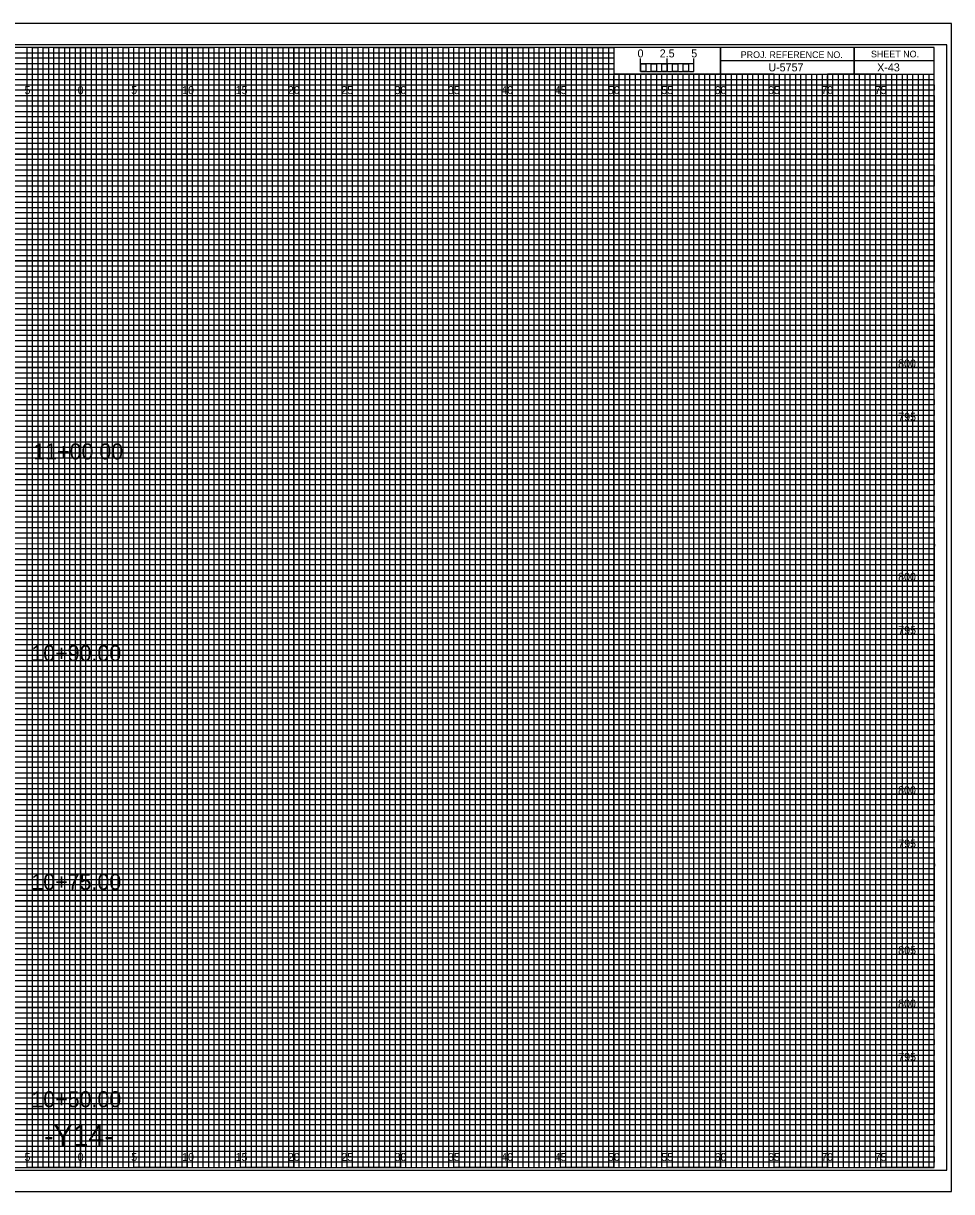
# Model space of a CAD drawing. Extents: x -7 to 162, y -2 to 107.
# Drawn here: x 74.6 to 161.7, y -2.3 to 107.3 of the extents above; entities that cross this region are included whole.
import ezdxf

# ---------------------------------------------------------------- set-up
doc = ezdxf.new("R2010")
doc.units = 0
for name, color, linetype in [('Exist CMT Pavement', 7, 'Continuous'), ('Exist Cross Section Cell', 7, 'Continuous'), ('Exist XS Center Line Elevation Label', 7, 'Continuous'), ('Prop CMT Conc Surface', 7, 'Continuous'), ('Prop CMT Concrete Structures', 7, 'Continuous'), ('Prop CMT Pvmt Course 1 CG', 7, 'Continuous'), ('Prop CMT Pvmt Course 2 Wedge', 7, 'Continuous'), ('Prop XS Alignment Label', 7, 'Continuous'), ('Prop XS Bar Scale Labels', 7, 'Continuous'), ('Prop XS Hydro Elevations', 7, 'Continuous'), ('Prop XS SE Text', 7, 'Continuous'), ('Prop XS Side Slope Text', 7, 'Continuous'), ('Sheet Cross Section Grid Minor 2 CELL', 7, 'Continuous'), ('Sheet Cross Section Scale CELL', 7, 'Continuous'), ('Sheet DOT Grid CELL', 7, 'Continuous'), ('Sheet Plot Border Inside CELL', 7, 'Continuous'), ('Sheet Plot Border Outside CELL', 7, 'Continuous')]:
    doc.layers.add(name, color=color, linetype=linetype)

msp = doc.modelspace()

# ---------------------------------------------------------------- linework, layer by layer
at = {"layer": 'Exist Cross Section Cell'}
for p, q in [((75, 105), (70, 105)), ((75, 0), (75, 105)), ((85, 105), (80, 105)), ((80, 105), (80, 0)), ((85, 0), (85, 105)), ((95, 105), (90, 105)), ((90, 105), (90, 0)), ((95, 0), (95, 105)), ((105, 105), (100, 105)), ((100, 105), (100, 0)), ((105, 0), (105, 105)), ((115, 105), (110, 105)), ((110, 105), (110, 0)), ((115, 0), (115, 105)), ((125, 105), (120, 105)), ((120, 105), (120, 0)), ((125, 0), (125, 105)), ((130, 105), (130, 0)), ((135, 0), (135, 102.5)), ((145, 102.5), (140, 102.5)), ((140, 102.5), (140, 0)), ((145, 0), (145, 102.5)), ((155, 102.5), (150, 102.5)), ((150, 102.5), (150, 0)), ((155, 0), (155, 102.5)), ((80, 0), (75, 0)), ((90, 0), (85, 0)), ((100, 0), (95, 0)), ((110, 0), (105, 0)), ((120, 0), (115, 0)), ((130, 0), (125, 0)), ((140, 0), (135, 0)), ((150, 0), (145, 0)), ((160, 0), (155, 0)), ((160, 0), (160, 0))]:
    msp.add_line(p, q, dxfattribs=at)
for points in [[(0, 100), (160, 100), (160, 95), (0, 95)], [(0, 90), (160, 90), (160, 85), (0, 85)], [(0, 80), (160, 80), (160, 75), (0, 75)], [(0, 70), (160, 70), (160, 65), (0, 65)], [(0, 60), (160, 60), (160, 55), (0, 55)], [(0, 50), (160, 50), (160, 45), (0, 45)], [(0, 40), (160, 40), (160, 35), (0, 35)], [(0, 30), (160, 30), (160, 25), (0, 25)], [(0, 20), (160, 20), (160, 15), (0, 15)], [(0, 10), (160, 10), (160, 5), (0, 5)]]:
    msp.add_lwpolyline(points, dxfattribs=at)
at = {"layer": 'Exist XS Center Line Elevation Label'}
for points in [[(72.5, 0), (77.5, 0), (77.5, 105), (82.5, 105), (82.5, 0), (87.5, 0), (87.5, 105), (92.5, 105), (92.5, 0), (97.5, 0), (97.5, 105), (102.5, 105), (102.5, 0), (107.5, 0), (107.5, 105), (112.5, 105), (112.5, 0), (117.5, 0), (117.5, 105), (122.5, 105), (122.5, 0), (127.5, 0), (127.5, 105), (129.97, 105), (130, 105), (130, 102.5), (132.5, 102.5), (132.5, 0), (137.5, 0), (137.5, 102.5), (142.5, 102.5), (142.5, 0), (147.5, 0), (147.5, 102.5), (152.5, 102.5), (152.5, 0), (157.5, 0), (157.5, 102.5)], [(0, 102.5), (137.5, 102.5)], [(0, 92.5), (160, 92.5), (160, 97.5), (0, 97.5)], [(0, 82.5), (160, 82.5), (160, 87.5), (0, 87.5)], [(0, 72.5), (160, 72.5), (160, 77.5), (0, 77.5)], [(0, 62.5), (160, 62.5), (160, 67.5), (0, 67.5)], [(0, 52.5), (160, 52.5), (160, 57.5), (0, 57.5)], [(0, 42.5), (160, 42.5), (160, 47.5), (0, 47.5)], [(0, 32.5), (160, 32.5), (160, 37.5), (0, 37.5)], [(0, 22.5), (160, 22.5), (160, 27.5), (0, 27.5)], [(0, 12.5), (160, 12.5), (160, 17.5), (0, 17.5)], [(0, 2.5), (160, 2.5), (160, 7.5), (0, 7.5)]]:
    msp.add_lwpolyline(points, dxfattribs=at)
at = {"layer": 'Prop CMT Concrete Structures'}
for p, q in [((161.65, 107.25), (-6.7, 107.25)), ((-6.7, -2.25), (161.65, -2.25))]:
    msp.add_line(p, q, dxfattribs=at)
at = {"layer": 'Prop CMT Pvmt Course 2 Wedge'}
for p, q in [((152.5, 105), (152.5, 102.5)), ((152.5, 102.5), (152.5, 105)), ((160, 103.75), (140, 103.75)), ((140, 103.75), (140, 102.5)), ((140, 102.5), (160, 102.5))]:
    msp.add_line(p, q, dxfattribs=at)
for points in [[(160, 105), (0, 105), (0, 0), (160, 0)], [(140, 105), (130, 105), (130, 102.52), (140, 102.52)], [(160, 105), (140, 105), (140, 102.5), (160, 102.5)]]:
    msp.add_lwpolyline(points, close=True, dxfattribs=at)
at = {"layer": 'Prop XS Side Slope Text'}
for p, q in [((0, 104.5), (130, 104.5)), ((130, 104.5), (130, 103.99)), ((130, 103.99), (0, 103.99)), ((0, 103.5), (130, 103.5)), ((130, 102.95), (0, 102.95)), ((130, 103.5), (130, 102.95)), ((0, 102), (160, 102))]:
    msp.add_line(p, q, dxfattribs=at)
for points in [[(0, 101.5), (135, 101.5), (160, 101.5), (160, 101), (0, 101)], [(0, 100.5), (160, 100.5), (160, 99.5), (0, 99.5)], [(0, 99), (160, 99), (160, 98.5), (0, 98.49)], [(0, 98), (160, 98), (160, 97), (0, 97)], [(0, 96.5), (160, 96.5), (160, 96), (0, 96)], [(0, 95.5), (160, 95.5), (160, 94.5), (0, 94.5)], [(0, 94), (160, 94), (160, 93.5), (0, 93.5)], [(0, 93), (160, 93), (160, 92), (0, 92)], [(0, 91.5), (160, 91.5), (160, 91), (0, 91)], [(0, 90.5), (160, 90.5), (160, 89.5), (0, 89.5)], [(0, 89), (160, 89), (160, 88.5), (0, 88.5)], [(0, 88), (160, 88), (160, 86.98), (160, 86.5), (160, 86), (0, 86)], [(0, 87), (160, 87), (160, 86.5), (0, 86.5)], [(0, 85.5), (160, 85.5), (160, 84.5), (0, 84.52)], [(0, 84.52), (160, 84.5), (160, 84), (0, 84)], [(0, 83.5), (160, 83.5), (160, 83), (0, 83)], [(0, 82), (160, 82), (160, 81.5), (0, 81.5)], [(0, 81), (160, 81), (160, 80.5), (0, 80.5)], [(-0.04, 79.45), (160, 79.45), (160, 78.94), (-0.04, 78.94)], [(0, 78.5), (160, 78.5), (160, 78), (0, 78)], [(0, 77), (160, 77), (160, 76.5), (0, 76.5)], [(0, 76), (160, 76), (160, 75.5), (0, 75.5)], [(0, 74.5), (160, 74.5), (160, 74), (0, 74)], [(0, 73.5), (160, 73.5), (160, 73), (0, 73)], [(0, 72), (160, 72), (160, 71.5), (0, 71.5)], [(0, 71), (160, 71), (160, 70.5), (0, 70.5)], [(0, 69.5), (160, 69.5), (160, 68.99), (0, 69)], [(0, 68.5), (160, 68.5), (160, 68), (0, 68)], [(0, 67), (160, 67), (160, 66.5), (0, 66.5)], [(0, 66), (160, 66), (160, 65.5), (0, 65.5)], [(0, 64.5), (160, 64.5), (160, 64), (0, 64)], [(0, 63.5), (160, 63.5), (160, 63), (0, 63)], [(0, 62), (160, 62), (160, 61.5), (0, 61.5)], [(0, 61), (160, 61), (160, 60.5), (0, 60.5)], [(0, 59.5), (160, 59.5), (160, 59), (0, 59)], [(0, 58.5), (160.03, 58.45), (160, 58), (0, 58)], [(0, 57), (160, 57), (160, 56.5), (0, 56.5)], [(0, 56), (160, 56), (160, 55.5), (0, 55.5)], [(0, 54.5), (160, 54.5), (160, 54), (0, 54)], [(0, 53.5), (160, 53.5), (160, 53), (0, 53)], [(0, 52), (160, 52), (160, 51.5), (0, 51.5)], [(0, 51), (160, 51), (160, 50.5), (0, 50.5)], [(0, 49.5), (160, 49.5), (160, 49), (0, 49)], [(0, 48.5), (160, 48.5), (160, 48), (0, 48)], [(0, 47), (160, 47), (160, 46.5), (0, 46.5)], [(0, 46), (160, 46), (160, 45.5), (0, 45.5)], [(0, 44.5), (160, 44.5), (160, 44), (0, 44)], [(0, 43.5), (160, 43.5), (160, 43), (0, 43)], [(0, 42), (160, 42), (160, 41.5), (0, 41.5)], [(0, 41), (160, 41), (160, 40.5), (0, 40.5)], [(0, 39.5), (160, 39.5), (160, 38.99), (0, 39)], [(0, 38.5), (160, 38.5), (160, 38), (0, 38)], [(0, 37), (160, 37), (160, 36.5), (0, 36.5)], [(0, 36), (160, 36), (160, 35.5), (0, 35.5)], [(0, 34.5), (160, 34.5), (160, 34), (0, 34)], [(0, 33.5), (160, 33.5), (160, 33), (0, 33)], [(0, 32), (160, 32), (160, 31.5), (0, 31.5)], [(0, 31), (160, 31), (160, 30.5), (0, 30.5)], [(0, 29.5), (160, 29.5), (160, 29), (0, 29)], [(0, 28.5), (160.03, 28.46), (160, 28), (0, 28)], [(0, 27), (160, 27), (160, 26.5), (0, 26.5)], [(0, 26), (160, 26), (160, 25.5), (0, 25.5)], [(0, 24.5), (160, 24.5), (160, 24), (0, 24)], [(0, 23.5), (160, 23.5), (160, 23), (0, 23)], [(0, 22), (160, 22), (160, 21.5), (0, 21.5)], [(0, 21), (160, 21), (160, 20.5), (0, 20.5)], [(0, 19.5), (160, 19.5), (160, 19), (0, 19)], [(0, 18.5), (160, 18.5), (160, 18), (0, 18)], [(0, 17), (160, 17), (160, 16.5), (0, 16.5)], [(0, 16), (160, 16), (160, 15.5), (0, 15.5)], [(0, 14.5), (160, 14.5), (160, 14), (0, 14)], [(0, 13.5), (160, 13.5), (160, 13), (0, 13)], [(0, 12), (160, 12), (160, 11.5), (0, 11.5)], [(0, 11), (160, 11), (160, 10.5), (0, 10.5)], [(0, 9.5), (160, 9.5), (160, 9), (0, 9)], [(0, 8.5), (160, 8.5), (160, 8), (0, 8)], [(0, 7), (160, 7), (160, 6.5), (0, 6.5)], [(0, 6), (160, 6), (160, 5.5), (0, 5.5)], [(0, 4.5), (160, 4.5), (160, 4), (0, 4)], [(0, 3.5), (160, 3.5), (160, 3), (0, 3)], [(0, 2), (160, 2), (160, 1.5), (0, 1.5)], [(0, 1), (160, 1), (160, 0.5), (0, 0.5)]]:
    msp.add_lwpolyline(points, dxfattribs=at)
at = {"layer": 'Sheet Cross Section Grid Minor 2 CELL'}
for p, q in [((133.5, 102.5), (133, 102.5)), ((133, 102.5), (133, 0)), ((133.5, 0), (133.5, 102.5)), ((134.5, 102.5), (134, 102.5)), ((134, 102.5), (134, 0)), ((134.5, 0), (134.5, 102.5)), ((133, 0), (132.5, 0)), ((134, 0), (133.5, 0))]:
    msp.add_line(p, q, dxfattribs=at)
for points in [[(75, 0), (75.5, 0), (75.5, 105), (76, 105), (76, 0)], [(76, 0), (76.5, 0), (76.5, 105), (77, 105), (77, 0)], [(77.5, 0), (78, 0), (78, 105), (78.5, 105), (78.5, 0)], [(78.5, 0), (79, 0), (79, 105), (79.5, 105), (79.5, 0)], [(80, 0), (80.5, 0), (80.5, 105), (81, 105), (81, 0)], [(81, 0), (81.5, 0), (81.5, 105), (82, 105), (82, 0)], [(82.5, 0), (83, 0), (83, 105), (83.5, 105), (83.5, 0)], [(83.5, 0), (84, 0), (84, 105), (84.5, 105), (84.5, 0)], [(85, 0), (85.5, 0), (85.5, 105), (86, 105), (86, 0)], [(86, 0), (86.5, 0), (86.5, 105), (87, 105), (87, 0)], [(87.5, 0), (88, 0), (88, 105), (88.5, 105), (88.5, 0)], [(88.5, 0), (89, 0), (89, 105), (89.5, 105), (89.5, 0)], [(90, 0), (90.5, 0), (90.5, 105), (91, 105), (91, 0)], [(91, 0), (91.5, 0), (91.5, 105), (92, 105), (92, 0)], [(92.5, 0), (93, 0), (93, 105), (93.5, 105), (93.5, 0)], [(93.5, 0), (94, 0), (94, 105), (94.5, 105), (94.5, 0)], [(95, 0), (95.5, 0), (95.5, 105), (96, 105), (96, 0)], [(96, 0), (96.5, 0), (96.5, 105), (97, 105), (97, 0)], [(97.5, 0), (98, 0), (98, 105), (98.5, 105), (98.5, 0)], [(98.5, 0), (99, 0), (99, 105), (99.5, 105), (99.5, 0)], [(100, 0), (100.5, 0), (100.5, 105), (101, 105), (101, 0)], [(101, 0), (101.5, 0), (101.5, 105), (102, 105), (102, 0)], [(102.5, 0), (103, 0), (103, 105), (103.5, 105), (103.5, 0)], [(103.5, 0), (104, 0), (104, 105), (104.5, 105), (104.5, 0)], [(105, 0), (105.5, 0), (105.5, 105), (106, 105), (106, 0)], [(106, 0), (106.5, 0), (106.5, 105), (107, 105), (107, 0)], [(107.5, 0), (108, 0), (108, 105), (108.5, 105), (108.5, 0)], [(108.5, 0), (109, 0), (109, 105), (109.5, 105), (109.5, 0)], [(110, 0), (110.5, 0), (110.5, 105), (111, 105), (111, 0)], [(111, 0), (111.5, 0), (111.5, 105), (112, 105), (112, 0)], [(112.5, 0), (113, 0), (113, 105), (113.5, 105), (113.5, 0)], [(113.5, 0), (114, 0), (114, 105), (114.5, 105), (114.5, 0)], [(115, 0), (115.5, 0), (115.5, 105), (116, 105), (116, 0)], [(116, 0), (116.5, 0), (116.5, 105), (117, 105), (117, 0)], [(117.5, 0), (118, 0), (118, 105), (118.5, 105), (118.5, 0)], [(118.5, 0), (119, 0), (119, 105), (119.5, 105), (119.5, 0)], [(120, 0), (120.5, 0), (120.5, 105), (121, 105), (121, 0)], [(121, 0), (121.5, 0), (121.5, 105), (122, 105), (122, 0)], [(122.5, 0), (123, 0), (123, 105), (123.5, 105), (123.5, 0)], [(123.5, 0), (124, 0), (124, 105), (124.5, 105), (124.5, 0)], [(125, 0), (125.5, 0), (125.5, 105), (126, 105), (126, 0)], [(126, 0), (126.5, 0), (126.5, 105), (127, 105), (127, 0)], [(127.5, 0), (128, 0), (128, 105), (128.5, 105), (128.5, 0)], [(128.5, 0), (129, 0), (129, 105), (129.5, 105), (129.5, 0)], [(130, 0), (130.5, 0), (130.5, 102.5), (131.01, 102.5), (131.01, 0)], [(131, 0), (131.5, 0), (131.5, 102.5), (132, 102.5), (132, 0)], [(135, 0), (135.49, 0), (135.49, 102.5), (136, 102.5), (136, 0)], [(136, 0), (136.5, 0), (136.5, 102.5), (137.03, 102.5), (137.03, 0)], [(137.5, 0), (138, 0), (138, 102.5), (138.5, 102.5), (138.5, 0)], [(138.5, 0), (139, 0), (139, 102.5), (139.5, 102.5), (139.5, 0)], [(140, 0), (140.5, 0), (140.5, 102.5), (141, 102.5), (141, 0)], [(141, 0), (141.5, 0), (141.5, 102.5), (142, 102.5), (142, 0)], [(142.5, 0), (143, 0), (143, 102.5), (143.5, 102.5), (143.5, 0)], [(143.5, 0), (144, 0), (144, 102.5), (144.5, 102.5), (144.5, 0)], [(145, 0), (145.5, 0), (145.5, 102.5), (146, 102.5), (146, 0)], [(146, 0), (146.5, 0), (146.5, 102.5), (147, 102.5), (147, 0)], [(147.5, 0), (148, 0), (148, 102.5), (148.5, 102.5), (148.5, 0)], [(148.5, 0), (149, 0), (149, 102.5), (149.5, 102.5), (149.5, 0)], [(150, 0), (150.5, 0), (150.5, 102.5), (151, 102.5), (151, 0)], [(151, 0), (151.5, 0), (151.5, 102.5), (152, 102.5), (152, 0)], [(152.5, 0), (153, 0), (153, 102.5), (153.5, 102.5), (153.5, 0)], [(153.5, 0), (154, 0), (154, 102.5), (154.5, 102.5), (154.5, 0)], [(155, 0), (155.5, 0), (155.5, 102.5), (156, 102.5), (156, 0)], [(156, 0), (156.5, 0), (156.5, 102.5), (157, 102.5), (157, 0)], [(157.5, 0), (158, 0), (158, 102.5), (158.5, 102.5), (158.5, 0)], [(158.5, 0), (159, 0), (159, 102.5), (159.5, 102.5), (159.5, 0)]]:
    msp.add_lwpolyline(points, dxfattribs=at)
at = {"layer": 'Sheet Cross Section Scale CELL'}
for p, q in [((132.5, 102.75), (132.5, 103.95)), ((132.5, 103.45), (132.5, 103.95)), ((135, 102.75), (135, 103.95)), ((137.5, 102.75), (137.5, 103.95)), ((137.5, 103.45), (137.5, 103.95))]:
    msp.add_line(p, q, dxfattribs=at)
for points in [[(137.5, 103.45), (132.5, 103.45), (132.5, 102.75), (137.5, 102.75)], [(132.5, 103.45), (133, 103.45), (133, 102.75), (132.5, 102.75)], [(133.5, 103.45), (134, 103.45), (134, 102.75), (133.5, 102.75)], [(134.5, 103.45), (135, 103.45), (135, 102.75), (134.5, 102.75)], [(135.5, 103.45), (136, 103.45), (136, 102.75), (135.5, 102.75)], [(136.5, 103.45), (137, 103.45), (137, 102.75), (136.5, 102.75)]]:
    msp.add_lwpolyline(points, close=True, dxfattribs=at)
at = {"layer": 'Sheet DOT Grid CELL'}
for p, q in [((75, 0), (75, 105)), ((80, 0), (80, 105)), ((85, 0), (85, 105)), ((90, 0), (90, 105)), ((95, 0), (95, 105)), ((100, 0), (100, 105)), ((105, 0), (105, 105)), ((110, 0), (110, 105)), ((115, 0), (115, 105)), ((120, 0), (120, 105)), ((125, 0), (125, 105)), ((130, 0), (130, 102.34)), ((135, 0), (135, 102.34)), ((140, 0), (140, 102.34)), ((145, 0), (145, 102.34)), ((150, 0), (150, 102.34)), ((155, 0), (155, 102.34)), ((0, 100), (160, 100)), ((0, 95), (160, 95)), ((0, 90), (160, 90)), ((0, 85), (160, 85)), ((0, 80), (160, 80)), ((0, 75), (160, 75)), ((0, 70), (160, 70)), ((0, 65), (160, 65)), ((0, 60), (160, 60)), ((0, 55), (160, 55)), ((0, 50), (160, 50)), ((0, 45), (160, 45)), ((0, 40), (160, 40)), ((0, 35), (160, 35)), ((0, 30), (160, 30)), ((0, 25), (160, 25)), ((0, 20), (160, 20)), ((0, 15), (160, 15)), ((0, 10), (160, 10)), ((0, 5), (160, 5))]:
    msp.add_line(p, q, dxfattribs=at)
at = {"layer": 'Sheet Plot Border Inside CELL'}
msp.add_lwpolyline([(-5.4, -0.25), (161.2, -0.25), (161.2, 105.25), (-5.4, 105.25)], close=True, dxfattribs=at)
at = {"layer": 'Sheet Plot Border Outside CELL'}
msp.add_lwpolyline([(-6.7, -2.25), (161.65, -2.25), (161.65, 107.25), (-6.7, 107.25)], close=True, dxfattribs=at)

# ---------------------------------------------------------------- texts
at = {"layer": 'Exist CMT Pavement'}
for s, p in [('800', (156.63, 75)), ('795', (156.64, 70)), ('800', (156.63, 55)), ('795', (156.64, 50)), ('800', (156.63, 35)), ('795', (156.64, 30)), ('805', (156.64, 20)), ('800', (156.63, 15)), ('795', (156.64, 10))]:
    msp.add_text(s, height=0.75, dxfattribs=at).set_placement(p)
at = {"layer": 'Prop CMT Conc Surface'}
msp.add_text('X-43', height=0.75, dxfattribs=at).set_placement((154.67, 102.75))
at = {"layer": 'Prop CMT Pvmt Course 1 CG'}
for s, p in [('11+00.00', (75.57, 66.38)), ('10+90.00', (75.39, 47.47)), ('10+75.00', (75.39, 26.04)), ('10+50.00', (75.39, 5.66))]:
    msp.add_text(s, height=1.5, dxfattribs=at).set_placement(p)
at = {"layer": 'Prop CMT Pvmt Course 2 Wedge'}
for s, p in [('PROJ. REFERENCE NO.', (141.88, 104)), ('SHEET NO.', (154.09, 104.06))]:
    msp.add_text(s, height=0.625, dxfattribs=at).set_placement(p)
at = {"layer": 'Prop XS Alignment Label'}
msp.add_text('-Y14-', height=2, dxfattribs=at).set_placement((76.57, 2))
at = {"layer": 'Prop XS Bar Scale Labels'}
for s, p in [('2.5', (134.29, 104.06)), ('5', (137.24, 104.06))]:
    msp.add_text(s, height=0.75, dxfattribs=at).set_placement(p)
at = {"layer": 'Prop XS Hydro Elevations'}
msp.add_text('U-5757', height=0.75, dxfattribs=at).set_placement((144.47, 102.75))
at = {"layer": 'Prop XS SE Text'}
for s, p in [('5', (74.74, 100.62)), ('0', (79.73, 100.62)), ('0', (79.73, 100.62)), ('5', (84.74, 100.62)), ('10', (89.52, 100.62)), ('15', (94.53, 100.62)), ('20', (99.43, 100.62)), ('25', (104.44, 100.62)), ('30', (109.43, 100.62)), ('35', (114.44, 100.62)), ('40', (119.43, 100.62)), ('45', (124.44, 100.62)), ('50', (129.43, 100.62)), ('55', (134.44, 100.62)), ('60', (139.43, 100.62)), ('65', (144.44, 100.62)), ('70', (149.43, 100.62)), ('75', (154.44, 100.62)), ('5', (74.74, 0.62)), ('0', (79.73, 0.62)), ('0', (79.73, 0.62)), ('5', (84.74, 0.62)), ('10', (89.52, 0.62)), ('15', (94.53, 0.62)), ('20', (99.43, 0.62)), ('25', (104.44, 0.62)), ('30', (109.43, 0.62)), ('35', (114.44, 0.62)), ('40', (119.43, 0.62)), ('45', (124.44, 0.62)), ('50', (129.43, 0.62)), ('55', (134.44, 0.62)), ('60', (139.43, 0.62)), ('65', (144.44, 0.62)), ('70', (149.43, 0.62)), ('75', (154.44, 0.62))]:
    msp.add_text(s, height=0.75, dxfattribs=at).set_placement(p)
at = {"layer": 'Sheet Cross Section Scale CELL'}
msp.add_text('0', height=0.75, dxfattribs=at).set_placement((132.21, 104.06))

doc.saveas('drawing.dxf')
